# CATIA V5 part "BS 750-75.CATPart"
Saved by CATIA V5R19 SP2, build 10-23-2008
Part number: BS 750-75
Bounding box of the stored display mesh (mm): x -22.494 to 22.494, y -22.494 to 22.494, z 0 to 182
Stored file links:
  C:\Users\Bora\Desktop\3D Katı model\BS serisi\BS 750\BS 750-75.CATPart
  C:\Program Files\Dassault Systemes\B19\intel_a\reffiles\standard\MetricThickPitch.txt
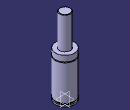
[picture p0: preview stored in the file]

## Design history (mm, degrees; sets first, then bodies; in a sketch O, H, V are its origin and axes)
Body1 (main body)
  Sketch1 on yz-plane, origin (0, 0, 0), H (0, 1, 0), V (0, 0, 1)
    point P3 (12.5, 181)
    point P5 (12.5, 181)
    point P7 (22.5, 92.5)
    point P8 (22.5, 90.5)
    point P12 (22.5, 90.5)
    point P13 (22.5, 92.5)
    line L1 (22.5, 0) -> (22.5, 4)
    line L2 (12.5, 181) -> (12.5, 106)
    arc A1 centre (11.5, 181) radius 1 from (12.5, 181) to (11.5, 182) ccw
    arc A2 centre (22.5, 91.5) radius 1 from (22.5, 92.5) to (22.5, 90.5) ccw
    line L3 (20, 7.5) -> (20, 4)
    line L4 (22.5, 7.5) -> (22.5, 90.5)
    line L5 (22.5, 92.5) -> (22.5, 106)
    line L6 (11.5, 182) -> (0, 182)
    point P15 (0, 182)
    line L7 (12.5, 106) -> (22.5, 106)
    line L8 (0, 0) -> (22.5, 0)
    line L9 (20, 7.5) -> (22.5, 7.5)
    line L10 (20, 4) -> (22.5, 4)
    coincidence: P15 V, P3 P5, P7 P13, P8 P12
    tangency: L6 A1
    horizontal: L7 H, L8 H, L9 H, L10 H
  Shaft1: profile Sketch1, axis Sketch1.V, angle 360
  Sketch2 on face of Shaft1 from Sketch1.L8, origin (0, 0, 0), H (1, 0, 0), V (0, -1, 0)
    point P1 (10, 0)
    distance P1 V = 10
  Hole1: placed by Sketch2, at (10, 0, 0) direction (0, 0, 1), diameter 6.647, depth 4, threaded "M8", thread diameter 8, thread depth 4, pitch 1.25
  CircPattern1: of Hole1, instances 2, angular step 180, axis from xy-plane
